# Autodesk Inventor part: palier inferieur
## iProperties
Created: 2002-03
Part Number: palier inferieur
Material: Par défaut
Document SubType Name: Modélisation
Designer: User
Control State: 0
Master: False
Checked Out: False
Shininess: 20.0
Length Units: 11269
Angle Units: 11279
Time Units: 11290
Mass Units: 11283
Length Display Precision: 3
Angle Display Precision: 2
Density: 0.0
Volumn: 0.0
Area: 0.0
PropertySet Name: Model Information
Author: User
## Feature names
1. Révolution1 [Revolution]
